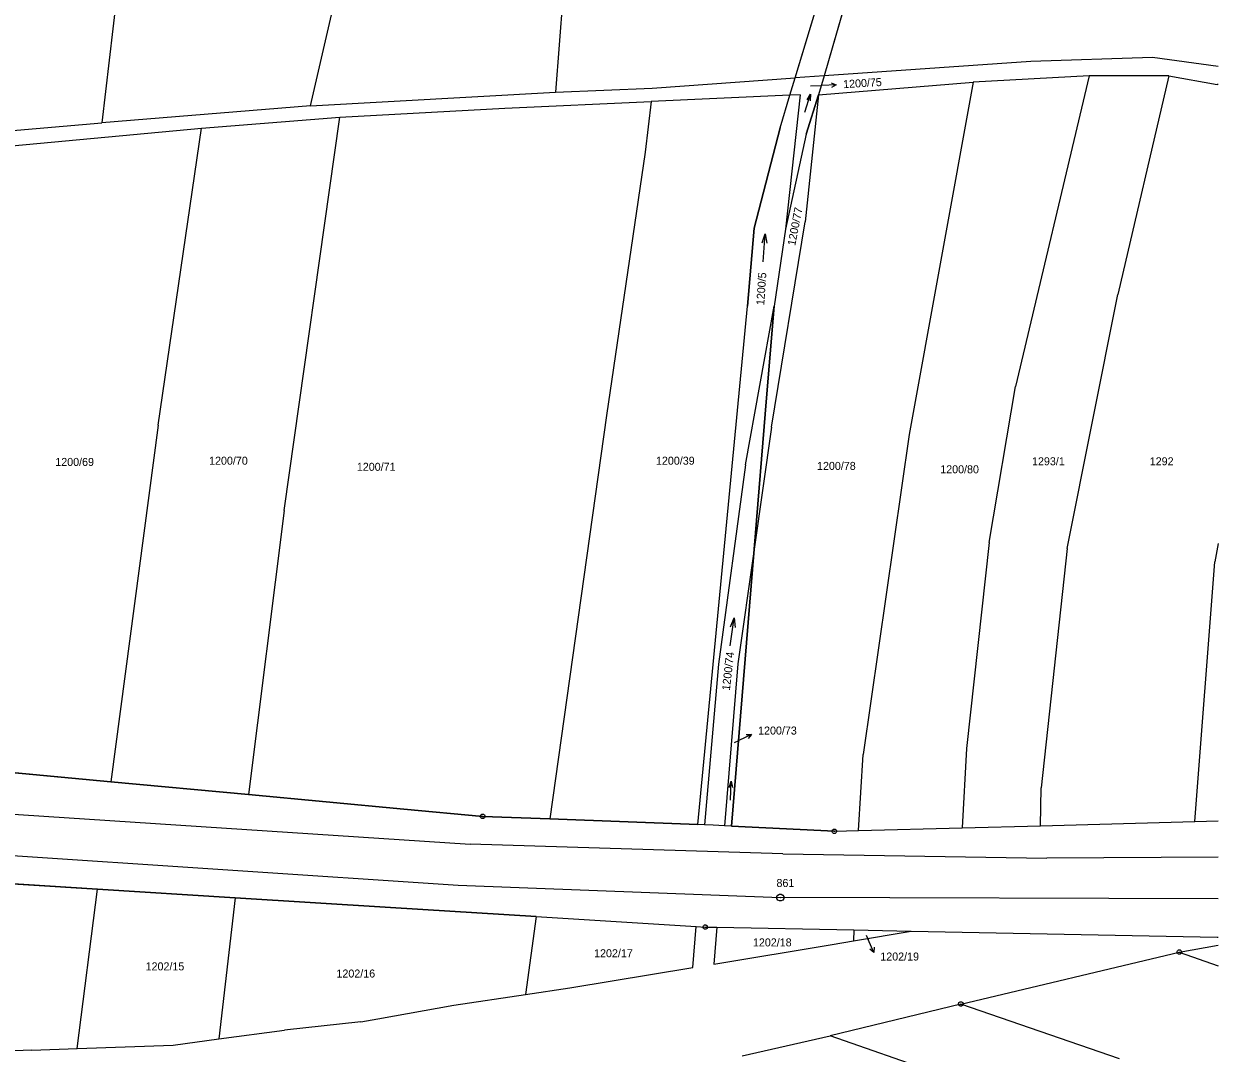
# Model space of a CAD drawing. Extents: x -779618 to -776429, y -1144546 to -1143350.
# Drawn here: x -776688.4 to -776434.8, y -1143887.2 to -1143668.7 of the extents above; entities that cross this region are included whole.
import ezdxf

# ---------------------------------------------------------------- set-up
doc = ezdxf.new("R2010")
doc.units = 0
for name, color, linetype in [('1', 7, 'Continuous'), ('11', 7, 'Continuous'), ('2', 7, 'Continuous'), ('3', 7, 'Continuous'), ('4', 7, 'Continuous'), ('7', 7, 'Continuous'), ('8', 7, 'Continuous')]:
    doc.layers.add(name, color=color, linetype=linetype)

msp = doc.modelspace()

# ---------------------------------------------------------------- linework, layer by layer
at = {"layer": '1'}
for p, q in [((-776524.6, -1143680.15), (-776499.1, -1143595.83)), ((-776627.48, -1143686.05), (-776615.06, -1143632.12)), ((-776509.07, -1143647.28), (-776518.43, -1143679.72)), ((-776572.97, -1143651.4), (-776575.52, -1143683.2)), ((-776668.44, -1143660.72), (-776671.82, -1143689.69)), ((-776474.57, -1143676.67), (-776518.43, -1143679.72)), ((-776448.72, -1143675.79), (-776474.57, -1143676.67)), ((-776434.77, -1143677.73), (-776448.72, -1143675.79)), ((-776554.93, -1143682.31), (-776524.6, -1143680.15)), ((-776525.72, -1143683.85), (-776524.6, -1143680.15)), ((-776518.43, -1143679.72), (-776524.6, -1143680.15)), ((-776518.43, -1143679.72), (-776519.6, -1143683.77)), ((-776519.6, -1143683.77), (-776486.77, -1143681.04)), ((-776486.77, -1143681.04), (-776500.41, -1143755.83)), ((-776462.15, -1143679.7), (-776486.77, -1143681.04)), ((-776462.15, -1143679.7), (-776477.79, -1143745.66)), ((-776445.25, -1143679.73), (-776462.15, -1143679.7)), ((-776445.25, -1143679.73), (-776456.06, -1143726.14)), ((-776445.25, -1143679.73), (-776434.94, -1143681.53)), ((-776434.77, -1143681.58), (-776434.94, -1143681.53)), ((-776627.48, -1143686.05), (-776575.52, -1143683.2)), ((-776575.52, -1143683.2), (-776554.93, -1143682.31)), ((-776525.72, -1143683.85), (-776555.2, -1143685.16)), ((-776527.81, -1143690.77), (-776525.72, -1143683.85)), ((-776523.53, -1143683.75), (-776526.66, -1143712.28)), ((-776523.53, -1143683.75), (-776525.72, -1143683.85)), ((-776519.6, -1143683.77), (-776522.48, -1143710.68)), ((-776522.25, -1143692.07), (-776519.6, -1143683.77)), ((-776627.48, -1143686.05), (-776671.82, -1143689.69)), ((-776621.25, -1143688.51), (-776586.24, -1143686.59)), ((-776586.24, -1143686.59), (-776555.2, -1143685.16)), ((-776555.2, -1143685.16), (-776556.43, -1143695.92)), ((-776650.69, -1143690.83), (-776621.25, -1143688.51)), ((-776633.12, -1143771.99), (-776621.25, -1143688.51)), ((-776695.8, -1143695), (-776650.69, -1143690.83)), ((-776695.6, -1143691.74), (-776671.82, -1143689.69)), ((-776659.83, -1143753.85), (-776650.69, -1143690.83)), ((-776527.81, -1143690.77), (-776533.27, -1143712.07)), ((-776522.25, -1143692.07), (-776526.66, -1143712.28)), ((-776556.43, -1143695.92), (-776564.64, -1143751.8)), ((-776533.27, -1143712.07), (-776534.71, -1143728.59)), ((-776529.59, -1143754.29), (-776522.48, -1143710.68)), ((-776526.66, -1143712.28), (-776529.06, -1143728.62)), ((-776466.86, -1143780.07), (-776456.06, -1143726.14)), ((-776545.27, -1143838.65), (-776534.71, -1143728.59)), ((-776535.14, -1143762.3), (-776529.06, -1143728.62)), ((-776530.66, -1143748.1), (-776529.06, -1143728.62)), ((-776483.39, -1143778.81), (-776477.79, -1143745.66)), ((-776533.29, -1143780.19), (-776530.66, -1143748.1)), ((-776564.64, -1143751.8), (-776576.67, -1143837.48)), ((-776659.83, -1143753.85), (-776669.89, -1143829.58)), ((-776529.59, -1143754.29), (-776533.29, -1143780.19)), ((-776500.41, -1143755.83), (-776510.15, -1143823.79)), ((-776535.14, -1143762.3), (-776540.87, -1143804.61)), ((-776633.12, -1143771.99), (-776640.68, -1143832.31)), ((-776538.12, -1143839.04), (-776533.29, -1143780.19)), ((-776533.29, -1143780.19), (-776536.77, -1143804.52)), ((-776483.39, -1143778.81), (-776488.2, -1143822.51)), ((-776466.86, -1143780.07), (-776472.33, -1143830.9)), ((-776434.77, -1143779), (-776435.5, -1143782.87)), ((-776439.72, -1143838.05), (-776435.5, -1143782.87)), ((-776540.87, -1143804.61), (-776543.86, -1143838.73)), ((-776536.77, -1143804.52), (-776539.57, -1143838.96)), ((-776511.15, -1143839.97), (-776510.15, -1143823.79)), ((-776488.2, -1143822.51), (-776489.11, -1143839.38)), ((-776669.89, -1143829.58), (-776712.16, -1143825.63)), ((-776640.68, -1143832.31), (-776669.89, -1143829.58)), ((-776472.47, -1143838.93), (-776472.33, -1143830.9)), ((-776607.67, -1143835.39), (-776640.68, -1143832.31)), ((-776590.95, -1143836.95), (-776607.67, -1143835.39)), ((-776576.67, -1143837.48), (-776590.95, -1143836.95)), ((-776545.27, -1143838.65), (-776576.67, -1143837.48)), ((-776543.86, -1143838.73), (-776545.27, -1143838.65)), ((-776542.02, -1143838.83), (-776543.86, -1143838.73)), ((-776539.57, -1143838.96), (-776542.02, -1143838.83)), ((-776538.12, -1143839.04), (-776539.57, -1143838.96)), ((-776516.26, -1143840.11), (-776538.12, -1143839.04)), ((-776489.11, -1143839.38), (-776472.47, -1143838.93)), ((-776472.47, -1143838.93), (-776439.72, -1143838.05)), ((-776439.72, -1143838.05), (-776434.77, -1143837.92)), ((-776516.26, -1143840.11), (-776511.15, -1143839.97)), ((-776511.15, -1143839.97), (-776489.11, -1143839.38)), ((-776672.72, -1143852.39), (-776715.66, -1143849.71)), ((-776677.09, -1143886.23), (-776672.72, -1143852.39)), ((-776643.49, -1143854.22), (-776672.72, -1143852.39)), ((-776643.49, -1143854.22), (-776646.96, -1143884.19)), ((-776610.51, -1143856.28), (-776643.49, -1143854.22)), ((-776579.58, -1143858.21), (-776610.51, -1143856.28)), ((-776579.58, -1143858.21), (-776581.88, -1143874.76)), ((-776579.58, -1143858.21), (-776545.63, -1143860.33)), ((-776546.34, -1143869.04), (-776545.63, -1143860.33)), ((-776545.63, -1143860.33), (-776543.68, -1143860.45)), ((-776543.68, -1143860.45), (-776541.24, -1143860.5)), ((-776541.24, -1143860.5), (-776541.84, -1143868.3)), ((-776541.24, -1143860.5), (-776512.12, -1143861.06)), ((-776512.12, -1143861.06), (-776512.23, -1143863.4)), ((-776512.23, -1143863.4), (-776499.94, -1143861.3)), ((-776512.12, -1143861.06), (-776499.94, -1143861.3)), ((-776499.94, -1143861.3), (-776434.96, -1143862.56)), ((-776541.84, -1143868.3), (-776516.72, -1143864.17)), ((-776516.72, -1143864.17), (-776512.23, -1143863.4)), ((-776443.01, -1143865.77), (-776434.77, -1143864.31)), ((-776434.96, -1143862.56), (-776434.77, -1143862.56)), ((-776489.41, -1143876.78), (-776443.01, -1143865.77)), ((-776443.01, -1143865.77), (-776434.77, -1143868.71)), ((-776572.45, -1143873.34), (-776546.34, -1143869.04)), ((-776597.08, -1143877.06), (-776581.88, -1143874.76)), ((-776581.88, -1143874.76), (-776572.45, -1143873.34)), ((-776613.22, -1143879.92), (-776597.08, -1143877.06)), ((-776489.41, -1143876.78), (-776517.13, -1143883.53)), ((-776455.73, -1143888.41), (-776489.41, -1143876.78)), ((-776646.96, -1143884.19), (-776633.03, -1143882.33)), ((-776616.82, -1143880.56), (-776633.03, -1143882.33)), ((-776616.82, -1143880.56), (-776613.22, -1143879.92)), ((-776656.66, -1143885.49), (-776646.96, -1143884.19)), ((-776535.81, -1143887.79), (-776517.13, -1143883.53)), ((-776494.43, -1143891.48), (-776517.13, -1143883.53)), ((-776686.67, -1143886.57), (-776701.86, -1143887.11)), ((-776686.67, -1143886.57), (-776677.09, -1143886.23)), ((-776677.09, -1143886.23), (-776656.66, -1143885.49))]:
    msp.add_line(p, q, dxfattribs=at)
at = {"layer": '11'}
for points in [[(-777005.26, -1143786.02), (-776947.51, -1143797.01), (-776924.63, -1143801.37), (-776885.75, -1143807.75), (-776878.28, -1143808.97), (-776877.42, -1143809.11), (-776742.31, -1143822.8), (-776740.58, -1143822.98), (-776712.16, -1143825.63), (-776669.89, -1143829.58), (-776640.68, -1143832.31), (-776607.67, -1143835.39), (-776590.95, -1143836.95), (-776576.67, -1143837.48), (-776545.27, -1143838.65), (-776534.71, -1143728.59), (-776533.27, -1143712.07), (-776527.81, -1143690.77), (-776525.72, -1143683.85), (-776524.6, -1143680.15), (-776499.1, -1143595.83)], [(-776509.07, -1143647.28), (-776518.43, -1143679.72), (-776519.6, -1143683.77), (-776522.25, -1143692.07), (-776526.66, -1143712.28), (-776529.06, -1143728.62), (-776530.66, -1143748.1), (-776533.29, -1143780.19), (-776538.12, -1143839.04), (-776516.26, -1143840.11), (-776511.15, -1143839.97), (-776489.11, -1143839.38), (-776472.47, -1143838.93), (-776439.72, -1143838.05), (-776434.77, -1143837.92)], [(-776746.01, -1143847.82), (-776715.66, -1143849.71), (-776672.72, -1143852.39), (-776643.49, -1143854.22), (-776610.51, -1143856.28), (-776579.58, -1143858.21), (-776545.63, -1143860.33), (-776543.68, -1143860.45), (-776541.24, -1143860.5), (-776512.12, -1143861.06), (-776499.94, -1143861.3), (-776434.96, -1143862.56), (-776434.77, -1143862.56)]]:
    msp.add_lwpolyline(points, dxfattribs=at)
at = {"layer": '3'}
for p, q in [((-776522.55, -1143687.46), (-776521.35, -1143683.62)), ((-776531.37, -1143719.22), (-776530.97, -1143713.24)), ((-776538.38, -1143800.71), (-776537.54, -1143794.77)), ((-776538.33, -1143833.51), (-776538.19, -1143829.49))]:
    msp.add_line(p, q, dxfattribs=at)
for points in [[(-776522.07, -1143684.8), (-776521.35, -1143683.62), (-776521.43, -1143685)], [(-776531.6, -1143715.2), (-776530.97, -1143713.24), (-776530.61, -1143715.27)], [(-776538.31, -1143796.68), (-776537.54, -1143794.77), (-776537.32, -1143796.82)], [(-776538.57, -1143830.82), (-776538.19, -1143829.49), (-776537.9, -1143830.84)]]:
    msp.add_lwpolyline(points, dxfattribs=at)
at = {"layer": '4'}
for p, q in [((-776693.94, -1143836.23), (-776593.63, -1143842.83)), ((-776527.2, -1143844.89), (-776593.63, -1143842.83)), ((-776694.77, -1143844.97), (-776596.12, -1143851.55)), ((-776527.2, -1143844.89), (-776471.18, -1143845.83)), ((-776434.77, -1143845.57), (-776471.18, -1143845.83)), ((-776596.12, -1143851.55), (-776527.73, -1143854.17)), ((-776434.77, -1143854.42), (-776527.73, -1143854.17))]:
    msp.add_line(p, q, dxfattribs=at)
at = {"layer": '7'}
for p, q in [((-776521.31, -1143681.87), (-776518.91, -1143681.77)), ((-776515.91, -1143681.64), (-776518.91, -1143681.77)), ((-776537.49, -1143821.26), (-776536.57, -1143820.83)), ((-776533.85, -1143819.57), (-776536.57, -1143820.83)), ((-776509.48, -1143862.13), (-776509.07, -1143863.09)), ((-776507.9, -1143865.85), (-776509.07, -1143863.09))]:
    msp.add_line(p, q, dxfattribs=at)
for points in [[(-776516.93, -1143681.19), (-776515.91, -1143681.64), (-776516.89, -1143682.18)], [(-776534.97, -1143819.53), (-776533.85, -1143819.57), (-776534.55, -1143820.44)], [(-776507.83, -1143864.74), (-776507.9, -1143865.85), (-776508.75, -1143865.13)]]:
    msp.add_lwpolyline(points, dxfattribs=at)
at = {"layer": '8'}
for p, q in [((-776591.07, -1143836.95), (-776590.83, -1143836.95)), ((-776516.38, -1143840.11), (-776516.14, -1143840.11)), ((-776527.78, -1143854.17), (-776527.68, -1143854.17)), ((-776543.8, -1143860.45), (-776543.56, -1143860.45)), ((-776443.13, -1143865.77), (-776442.89, -1143865.77)), ((-776489.53, -1143876.78), (-776489.29, -1143876.78))]:
    msp.add_line(p, q, dxfattribs=at)
for points in [[(-776590.8, -1143836.47), (-776590.55, -1143836.65), (-776590.45, -1143836.94), (-776590.55, -1143837.23), (-776590.8, -1143837.41), (-776591.11, -1143837.41), (-776591.36, -1143837.23), (-776591.46, -1143836.94), (-776591.36, -1143836.65), (-776591.11, -1143836.47)], [(-776516.11, -1143839.63), (-776515.86, -1143839.81), (-776515.76, -1143840.1), (-776515.86, -1143840.39), (-776516.11, -1143840.57), (-776516.42, -1143840.57), (-776516.67, -1143840.39), (-776516.77, -1143840.1), (-776516.67, -1143839.81), (-776516.42, -1143839.63)], [(-776527.54, -1143853.45), (-776527.2, -1143853.64), (-776527.01, -1143853.98), (-776527.01, -1143854.37), (-776527.2, -1143854.71), (-776527.54, -1143854.9), (-776527.93, -1143854.9), (-776528.27, -1143854.71), (-776528.46, -1143854.37), (-776528.46, -1143853.98), (-776528.27, -1143853.64), (-776527.93, -1143853.45)], [(-776543.53, -1143859.97), (-776543.28, -1143860.15), (-776543.18, -1143860.44), (-776543.28, -1143860.73), (-776543.53, -1143860.91), (-776543.84, -1143860.91), (-776544.09, -1143860.73), (-776544.19, -1143860.44), (-776544.09, -1143860.15), (-776543.84, -1143859.97)], [(-776442.86, -1143865.29), (-776442.61, -1143865.47), (-776442.51, -1143865.76), (-776442.61, -1143866.05), (-776442.86, -1143866.23), (-776443.17, -1143866.23), (-776443.42, -1143866.05), (-776443.52, -1143865.76), (-776443.42, -1143865.47), (-776443.17, -1143865.29)], [(-776489.26, -1143876.3), (-776489.01, -1143876.48), (-776488.91, -1143876.77), (-776489.01, -1143877.06), (-776489.26, -1143877.24), (-776489.57, -1143877.24), (-776489.82, -1143877.06), (-776489.92, -1143876.77), (-776489.82, -1143876.48), (-776489.57, -1143876.3)]]:
    msp.add_lwpolyline(points, close=True, dxfattribs=at)

# ---------------------------------------------------------------- texts
at = {"layer": '2'}
for s, height, p in [('1200/75', 0.1, (-776521.29, -1143681.87)), ('1200/70', 1.7, (-776649.05, -1143762.28)), ('1200/39', 1.7, (-776554.15, -1143762.28)), ('1293/1', 1.7, (-776474.29, -1143762.4)), ('1292', 1.7, (-776449.29, -1143762.4)), ('1200/69', 1.7, (-776681.71, -1143762.54)), ('1200/71', 1.7, (-776617.67, -1143763.57)), ('1200/78', 1.7, (-776519.95, -1143763.38)), ('1200/80', 1.7, (-776493.78, -1143764.1)), ('1200/73', 0.1, (-776537.47, -1143821.26)), ('1202/19', 0.1, (-776509.46, -1143862.13)), ('1202/18', 1.7, (-776533.56, -1143864.55)), ('1202/17', 1.7, (-776567.29, -1143866.85)), ('1202/15', 1.7, (-776662.53, -1143869.64)), ('1202/16', 1.7, (-776622, -1143871.16))]:
    msp.add_text(s, height=height, dxfattribs=at).set_placement(p)
for s, rotation, p in [('1200/77', 78.9536, (-776524.58, -1143715.87)), ('1200/5', 86.1729, (-776531.16, -1143728.45)), ('1200/74', 83.5372, (-776538.46, -1143810.29))]:
    msp.add_text(s, height=1.7, rotation=rotation, dxfattribs=at).set_placement(p)
at = {"layer": '7'}
msp.add_text('1200/75', height=1.7, rotation=3.4377, dxfattribs=at).set_placement((-776514.35, -1143682.35))
for s, p in [('1200/73', (-776532.46, -1143819.57)), ('1202/19', (-776506.51, -1143867.55))]:
    msp.add_text(s, height=1.7, dxfattribs=at).set_placement(p)
at = {"layer": '8'}
msp.add_text('861', height=1.7, dxfattribs=at).set_placement((-776528.56, -1143851.93))

doc.saveas('drawing.dxf')
